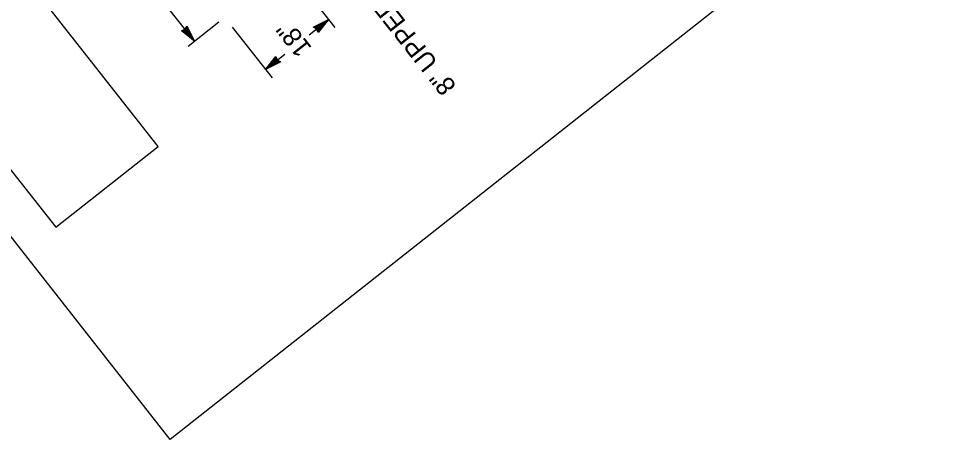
# Model space of a CAD drawing. Extents: x 672239 to 673995, y 1673540 to 1675195.
# Drawn here: x 672345.2 to 672553.6, y 1674783.8 to 1674877.9 of the extents above; entities that cross this region are included whole.
import ezdxf

# ---------------------------------------------------------------- set-up
doc = ezdxf.new("R2010")
doc.units = 0
doc.layers.add('C-ALGN-SYMB', color=7, linetype='Continuous')
doc.layers.add('C-HELI-SIDE', color=7, linetype='Continuous')

msp = doc.modelspace()

# ---------------------------------------------------------------- linework, layer by layer
at = {"layer": 'C-ALGN-SYMB'}
for p, q in [((672675.29, 1675017.25), (672379.17, 1674783.8)), ((672379.17, 1674783.8), (672239.38, 1674961.12)), ((672384.61, 1674872.8), (672372.64, 1674887.98)), ((672407.15, 1674887.12), (672415.98, 1674875.92)), ((672390.07, 1674877.1), (672383.17, 1674871.66)), ((672410.27, 1674874.23), (672414.61, 1674877.65)), ((672411.15, 1674875.95), (672414.61, 1674877.65)), ((672411.34, 1674876), (672414.19, 1674877.3)), ((672411.51, 1674875.97), (672414.35, 1674877.39)), ((672414.61, 1674877.65), (672412.29, 1674874.75)), ((672414.39, 1674877.42), (672412.31, 1674874.89)), ((672414.04, 1674877.14), (672412.31, 1674875.06)), ((672414.14, 1674877.36), (672413.34, 1674876.93)), ((672413.34, 1674876.93), (672414.04, 1674877.14)), ((672414.35, 1674877.39), (672414.14, 1674877.36)), ((672414.19, 1674877.3), (672414.39, 1674877.42)), ((672381.7, 1674875.12), (672382.46, 1674875.51)), ((672384.61, 1674872.8), (672381.7, 1674875.12)), ((672381.85, 1674875.1), (672382.41, 1674875.44)), ((672384.37, 1674873.01), (672381.85, 1674875.1)), ((672382.02, 1674875.1), (672382.28, 1674875.24)), ((672384.1, 1674873.37), (672382.02, 1674875.1)), ((672382.15, 1674875.1), (672382.85, 1674875.78)), ((672383.87, 1674873.66), (672382.15, 1674875.1)), ((672382.28, 1674875.24), (672382.85, 1674875.78)), ((672382.28, 1674875.14), (672382.79, 1674875.6)), ((672384, 1674873.58), (672382.28, 1674875.14)), ((672382.41, 1674875.44), (672382.89, 1674876.11)), ((672382.69, 1674875.52), (672382.41, 1674875.14)), ((672382.41, 1674875.14), (672383.17, 1674874.64)), ((672382.43, 1674875.08), (672382.75, 1674875.44)), ((672383.54, 1674874.09), (672382.43, 1674875.08)), ((672382.46, 1674875.51), (672382.77, 1674875.75)), ((672382.55, 1674875.05), (672382.7, 1674875.33)), ((672383.27, 1674874.48), (672382.55, 1674875.05)), ((672382.63, 1674875.08), (672382.7, 1674875.16)), ((672382.97, 1674874.81), (672382.63, 1674875.08)), ((672382.7, 1674875.16), (672382.69, 1674875.52)), ((672382.7, 1674875.33), (672382.97, 1674874.81)), ((672382.75, 1674875.44), (672383.27, 1674874.48)), ((672382.77, 1674875.75), (672382.96, 1674876.07)), ((672382.79, 1674875.6), (672383.54, 1674874.09)), ((672382.89, 1674876.11), (672382.82, 1674875.89)), ((672382.82, 1674875.89), (672382.92, 1674875.9)), ((672382.85, 1674875.78), (672383.87, 1674873.66)), ((672382.85, 1674875.78), (672384, 1674873.58)), ((672382.91, 1674876.26), (672384.61, 1674872.8)), ((672382.92, 1674875.9), (672384.34, 1674873.06)), ((672382.96, 1674876.07), (672384.25, 1674873.22)), ((672393.01, 1674875.98), (672401.97, 1674864.62)), ((672411.97, 1674875.46), (672411.29, 1674875.93)), ((672411.29, 1674875.93), (672411.51, 1674875.87)), ((672411.65, 1674875.82), (672411.34, 1674876)), ((672411.51, 1674875.87), (672411.51, 1674875.97)), ((672411.63, 1674875.89), (672413.82, 1674877.04)), ((672411.63, 1674875.89), (672413.75, 1674876.92)), ((672412.17, 1674875.32), (672411.63, 1674875.89)), ((672412.31, 1674875.19), (672411.63, 1674875.89)), ((672411.9, 1674875.51), (672411.65, 1674875.82)), ((672411.81, 1674875.83), (672413.32, 1674876.58)), ((672412.27, 1674875.33), (672411.81, 1674875.83)), ((672412.24, 1674875.74), (672411.89, 1674875.73)), ((672411.89, 1674875.73), (672412.26, 1674875.46)), ((672412.29, 1674874.75), (672411.9, 1674875.51)), ((672411.97, 1674875.79), (672412.93, 1674876.31)), ((672412.32, 1674875.47), (672411.97, 1674875.79)), ((672412.31, 1674874.89), (672411.97, 1674875.46)), ((672412.08, 1674875.75), (672412.59, 1674876.02)), ((672412.36, 1674875.6), (672412.08, 1674875.75)), ((672412.31, 1674875.06), (672412.17, 1674875.32)), ((672412.33, 1674875.68), (672412.24, 1674875.74)), ((672412.26, 1674875.46), (672412.77, 1674876.22)), ((672413.82, 1674877.04), (672412.27, 1674875.33)), ((672413.75, 1674876.92), (672412.31, 1674875.19)), ((672413.32, 1674876.58), (672412.32, 1674875.47)), ((672412.59, 1674876.02), (672412.33, 1674875.68)), ((672412.93, 1674876.31), (672412.36, 1674875.6)), ((672412.77, 1674876.22), (672413.02, 1674876.32)), ((672413.38, 1674876.67), (672412.95, 1674876.46)), ((672413.02, 1674876.32), (672413.38, 1674876.67)), ((672383.17, 1674874.64), (672383.27, 1674874.38)), ((672383.27, 1674874.38), (672383.62, 1674874.02)), ((672383.62, 1674874.02), (672383.41, 1674874.46)), ((672384.31, 1674873.26), (672383.89, 1674874.06)), ((672383.89, 1674874.06), (672384.1, 1674873.37)), ((672384.25, 1674873.22), (672384.37, 1674873.01)), ((672384.34, 1674873.06), (672384.31, 1674873.26)), ((672400.47, 1674866.51), (672404.8, 1674869.92)), ((672400.47, 1674866.51), (672402.8, 1674869.42)), ((672400.69, 1674866.75), (672402.78, 1674869.27)), ((672401.04, 1674867.02), (672402.77, 1674869.1)), ((672401.26, 1674867.12), (672402.82, 1674868.84)), ((672401.33, 1674867.25), (672402.78, 1674868.97)), ((672402.77, 1674869.1), (672402.91, 1674868.84)), ((672402.78, 1674869.27), (672403.12, 1674868.71)), ((672402.78, 1674868.97), (672403.46, 1674868.27)), ((672402.8, 1674869.42), (672403.19, 1674868.66)), ((672402.82, 1674868.84), (672403.28, 1674868.33)), ((672402.91, 1674868.84), (672403.46, 1674868.27)), ((672403.94, 1674868.21), (672400.47, 1674866.51)), ((672400.89, 1674866.87), (672400.69, 1674866.75)), ((672403.58, 1674868.2), (672400.73, 1674866.78)), ((672400.73, 1674866.78), (672400.94, 1674866.81)), ((672403.74, 1674868.16), (672400.89, 1674866.87)), ((672400.94, 1674866.81), (672401.74, 1674867.23)), ((672401.74, 1674867.23), (672401.04, 1674867.02)), ((672403.46, 1674868.27), (672401.26, 1674867.12)), ((672403.46, 1674868.27), (672401.33, 1674867.25)), ((672402.06, 1674867.85), (672401.7, 1674867.5)), ((672401.7, 1674867.5), (672402.13, 1674867.71)), ((672401.77, 1674867.59), (672402.76, 1674868.69)), ((672403.28, 1674868.33), (672401.77, 1674867.59)), ((672402.31, 1674867.95), (672402.06, 1674867.85)), ((672402.15, 1674867.85), (672402.73, 1674868.57)), ((672403.11, 1674868.37), (672402.15, 1674867.85)), ((672402.82, 1674868.71), (672402.31, 1674867.95)), ((672402.49, 1674868.15), (672402.76, 1674868.49)), ((672403.01, 1674868.42), (672402.49, 1674868.15)), ((672402.73, 1674868.57), (672403.01, 1674868.42)), ((672402.76, 1674868.69), (672403.11, 1674868.37)), ((672402.76, 1674868.49), (672402.84, 1674868.42)), ((672403.2, 1674868.43), (672402.82, 1674868.71)), ((672402.84, 1674868.42), (672403.2, 1674868.43)), ((672403.12, 1674868.71), (672403.79, 1674868.23)), ((672403.19, 1674868.66), (672403.43, 1674868.35)), ((672403.43, 1674868.35), (672403.74, 1674868.16)), ((672403.79, 1674868.23), (672403.57, 1674868.3)), ((672403.57, 1674868.3), (672403.58, 1674868.2))]:
    msp.add_line(p, q, dxfattribs=at)
at = {"layer": 'C-HELI-SIDE'}
msp.add_lwpolyline([(672376.49, 1674849.31), (672302.96, 1674942.58), (672280.01, 1674924.48), (672353.54, 1674831.21)], close=True, dxfattribs=at)

# ---------------------------------------------------------------- texts
at = {"layer": 'C-ALGN-SYMB'}
for s, p in [('8" UPPERCASE', (672443.38, 1674862.84)), ('18"', (672411.02, 1674871.35))]:
    msp.add_text(s, height=4.2, rotation=128.2505, dxfattribs=at).set_placement(p)

doc.saveas('drawing.dxf')
